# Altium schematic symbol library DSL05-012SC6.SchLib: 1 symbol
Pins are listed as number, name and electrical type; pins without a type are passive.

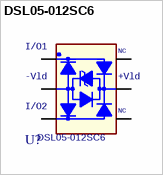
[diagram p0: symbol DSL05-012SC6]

## DSL05-012SC6
designator U?
footprint ST_SOT23-6L
pins: 1 I/O1, 2 -VLD, 3 I/O2, 4 NC, 5 +VLD, 6 NC1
